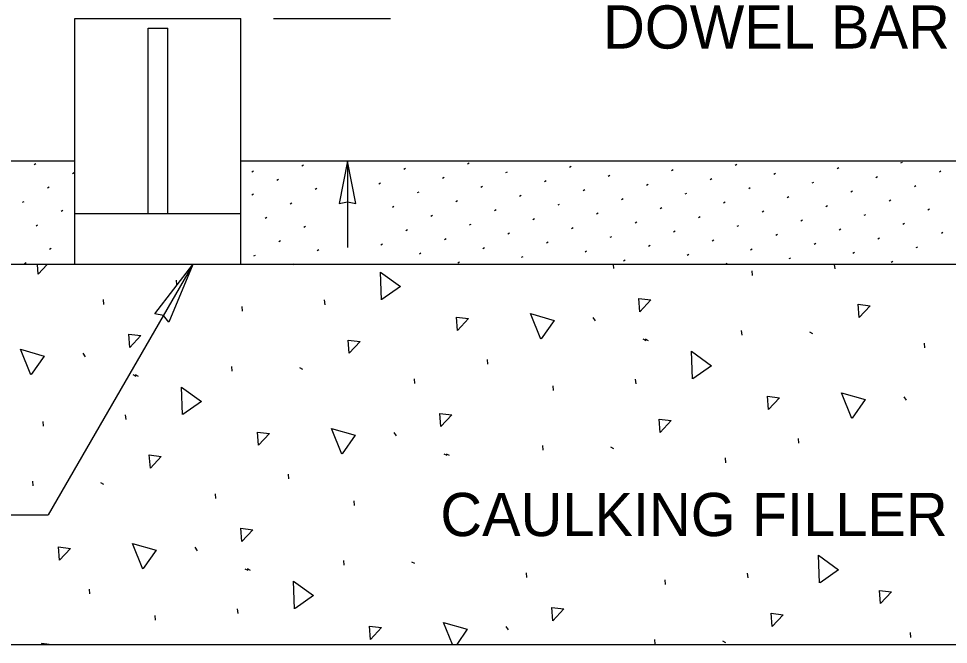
# Model space of a CAD drawing. Extents: x 99862 to 104211, y 98939 to 105076.
# Drawn here: x 100951.2 to 101295.5, y 103804.6 to 104036.3 of the extents above; entities that cross this region are included whole.
import ezdxf

# ---------------------------------------------------------------- set-up
doc = ezdxf.new("R2010")
doc.units = 0
for name, color, linetype in [('Level 1', 7, 'Continuous'), ('Level 15', 7, 'Continuous'), ('Level 2', 7, 'Continuous'), ('Level 20', 7, 'Continuous'), ('Level 3', 7, 'Continuous'), ('Level 4', 7, 'Continuous'), ('Level 6', 7, 'Continuous')]:
    doc.layers.add(name, color=color, linetype=linetype)

msp = doc.modelspace()

# ---------------------------------------------------------------- linework, layer by layer
at = {"layer": 'Level 1'}
msp.add_line((102063.85, 103945.23), (100698.76, 103945.23), dxfattribs=at)
msp.add_line((102063.85, 103945.23), (100698.76, 103945.23), dxfattribs=at)
msp.add_lwpolyline([(100169.63, 103804.62), (100694.77, 103804.62), (102647.84, 103804.62)], dxfattribs=at)
at = {"layer": 'Level 15'}
for p, q in [((101045.5, 104036.29), (101088.91, 104036.29)), ((101072.91, 103983.52), (101072.91, 103951.52)), ((101015.65, 103945.23), (100962.16, 103852.58)), ((100946.16, 103852.58), (100962.16, 103852.58))]:
    msp.add_line(p, q, dxfattribs=at)
for points in [[(101072.91, 103983.52), (101069.82, 103967.79), (101072.91, 103968.52), (101075.99, 103967.79)], [(101015.65, 103945.23), (101006.82, 103923.97), (101004.76, 103926.38), (101001.65, 103926.95)]]:
    msp.add_lwpolyline(points, close=True, dxfattribs=at)
at = {"layer": 'Level 2'}
for p, q in [((100972, 103983.52), (100862.71, 103983.52)), ((101375.26, 103983.52), (101033.5, 103983.52))]:
    msp.add_line(p, q, dxfattribs=at)
at = {"layer": 'Level 3'}
for p, q in [((100956.88, 103982.29), (100957.49, 103982.64)), ((101056.02, 103981.79), (101056.63, 103982.14)), ((101093.83, 103980.53), (101094.43, 103980.88)), ((101117.36, 103982.57), (101117.97, 103982.92)), ((101155.16, 103981.3), (101155.77, 103981.65)), ((101216.5, 103982.07), (101217.11, 103982.42)), ((101254.3, 103980.8), (101254.91, 103981.15)), ((101277.84, 103982.84), (101278.45, 103983.19)), ((100971.15, 103978.98), (100971.75, 103979.33)), ((101037.49, 103979.59), (101038.1, 103979.94)), ((101108.09, 103977.22), (101108.7, 103977.57)), ((101131.63, 103979.26), (101132.23, 103979.61)), ((101169.43, 103977.99), (101170.04, 103978.34)), ((101192.97, 103980.03), (101193.57, 103980.38)), ((101207.23, 103976.72), (101207.84, 103977.07)), ((101230.77, 103978.76), (101231.38, 103979.11)), ((101268.57, 103977.49), (101269.18, 103977.84)), ((101292.11, 103979.53), (101292.71, 103979.88)), ((100961.88, 103973.63), (100962.49, 103973.98)), ((101046.75, 103976.44), (101047.36, 103976.79)), ((101084.56, 103975.17), (101085.16, 103975.52)), ((101122.36, 103973.91), (101122.97, 103974.26)), ((101145.9, 103975.95), (101146.5, 103976.3)), ((101183.7, 103974.68), (101184.31, 103975.03)), ((101221.5, 103973.41), (101222.11, 103973.76)), ((101245.04, 103975.45), (101245.64, 103975.8)), ((101282.84, 103974.18), (101283.45, 103974.53)), ((101037.49, 103971.09), (101038.09, 103971.44)), ((101061.02, 103973.13), (101061.63, 103973.48)), ((101098.83, 103971.86), (101099.43, 103972.21)), ((101136.63, 103970.6), (101137.23, 103970.95)), ((101160.16, 103972.64), (101160.77, 103972.99)), ((101197.97, 103971.37), (101198.57, 103971.72)), ((101235.77, 103970.1), (101236.38, 103970.45)), ((101259.3, 103972.14), (101259.91, 103972.49)), ((100952.61, 103968.28), (100953.22, 103968.63)), ((101051.75, 103967.78), (101052.36, 103968.13)), ((101089.56, 103966.51), (101090.16, 103966.86)), ((101113.09, 103968.56), (101113.7, 103968.91)), ((101150.9, 103967.29), (101151.5, 103967.64)), ((101174.43, 103969.33), (101175.04, 103969.68)), ((101212.23, 103968.06), (101212.84, 103968.41)), ((101250.04, 103966.79), (101250.64, 103967.14)), ((101273.57, 103968.83), (101274.18, 103969.18)), ((100966.88, 103964.97), (100967.49, 103965.32)), ((101103.83, 103963.2), (101104.43, 103963.55)), ((101127.36, 103965.25), (101127.97, 103965.6)), ((101165.16, 103963.98), (101165.77, 103964.33)), ((101188.7, 103966.02), (101189.31, 103966.37)), ((101226.5, 103964.75), (101227.11, 103965.1)), ((101264.3, 103963.48), (101264.91, 103963.83)), ((101287.84, 103965.52), (101288.45, 103965.87)), ((100957.61, 103959.62), (100958.22, 103959.97)), ((101042.49, 103962.43), (101043.09, 103962.78)), ((101118.09, 103959.89), (101118.7, 103960.24)), ((101141.63, 103961.94), (101142.23, 103962.29)), ((101179.43, 103960.67), (101180.04, 103961.02)), ((101202.97, 103962.71), (101203.57, 103963.06)), ((101240.77, 103961.44), (101241.38, 103961.79)), ((101278.57, 103960.17), (101279.18, 103960.52)), ((101056.75, 103959.12), (101057.36, 103959.47)), ((101094.56, 103957.85), (101095.16, 103958.2)), ((101132.36, 103956.59), (101132.97, 103956.94)), ((101155.9, 103958.63), (101156.5, 103958.98)), ((101193.7, 103957.36), (101194.31, 103957.71)), ((101217.23, 103959.4), (101217.84, 103959.75)), ((101231.5, 103956.09), (101232.11, 103956.44)), ((101255.04, 103958.13), (101255.64, 103958.48)), ((101292.84, 103956.86), (101293.45, 103957.21)), ((101047.49, 103953.77), (101048.09, 103954.12)), ((101108.83, 103954.54), (101109.43, 103954.89)), ((101146.63, 103953.28), (101147.23, 103953.63)), ((101170.16, 103955.32), (101170.77, 103955.67)), ((101207.97, 103954.05), (101208.57, 103954.4)), ((101245.77, 103952.78), (101246.38, 103953.13)), ((101269.3, 103954.82), (101269.91, 103955.17)), ((100962.61, 103950.96), (100963.22, 103951.31)), ((101061.75, 103950.46), (101062.36, 103950.81)), ((101085.29, 103952.5), (101085.9, 103952.85)), ((101099.56, 103949.19), (101100.16, 103949.54)), ((101123.09, 103951.23), (101123.7, 103951.58)), ((101160.9, 103949.97), (101161.5, 103950.32)), ((101184.43, 103952.01), (101185.04, 103952.36)), ((101222.23, 103950.74), (101222.84, 103951.09)), ((101260.04, 103949.47), (101260.64, 103949.82)), ((101283.57, 103951.51), (101284.18, 103951.86)), ((101038.22, 103948.42), (101038.83, 103948.77)), ((101113.83, 103945.88), (101114.43, 103946.23)), ((101137.36, 103947.93), (101137.97, 103948.28)), ((101175.16, 103946.66), (101175.77, 103947.01)), ((101198.7, 103948.7), (101199.31, 103949.05)), ((101236.5, 103947.43), (101237.11, 103947.78)), ((101274.3, 103946.16), (101274.91, 103946.51)), ((100953.35, 103945.61), (100953.95, 103945.96)), ((101052.69, 103945.23), (101053.09, 103945.46)), ((101212.97, 103945.39), (101213.57, 103945.74))]:
    msp.add_line(p, q, dxfattribs=at)
at = {"layer": 'Level 4'}
for p, q in [((101171.6, 103943.74), (101171.44, 103945.23)), ((101222.91, 103941.17), (101222.73, 103942.91)), ((101253.49, 103943.62), (101253.32, 103945.23)), ((101009.78, 103937.7), (101009.6, 103939.44)), ((100982.76, 103930.51), (100982.58, 103932.25)), ((101034.08, 103927.94), (101033.89, 103929.68)), ((101064.65, 103930.39), (101064.47, 103932.13)), ((101163.74, 103925.64), (101164.69, 103924.35)), ((101219.08, 103919.04), (101218.9, 103920.78)), ((101243.99, 103920.3), (101245.14, 103919.73)), ((101182.31, 103917.73), (101183.45, 103917.16)), ((101183.12, 103917.73), (101184.27, 103917.16)), ((101286.75, 103914.43), (101286.57, 103916.17)), ((100974.9, 103912.42), (100975.85, 103911.12)), ((101124.94, 103908.39), (101124.75, 103910.13)), ((101030.24, 103905.81), (101030.06, 103907.55)), ((101055.15, 103907.07), (101056.3, 103906.5)), ((100993.47, 103904.5), (100994.62, 103903.93)), ((100994.29, 103904.5), (100995.44, 103903.94)), ((101097.92, 103901.2), (101097.73, 103902.94)), ((101179.81, 103901.08), (101179.63, 103902.82)), ((101149.24, 103898.63), (101149.05, 103900.37)), ((101278.9, 103896.33), (101279.85, 103895.04)), ((100990.98, 103887.86), (100990.79, 103889.6)), ((100960.4, 103885.41), (100960.22, 103887.15)), ((101090.06, 103883.11), (101091.01, 103881.81)), ((101240.1, 103879.08), (101239.91, 103880.82)), ((101145.4, 103876.5), (101145.22, 103878.24)), ((101170.31, 103877.76), (101171.46, 103877.19)), ((101108.63, 103875.19), (101109.78, 103874.62)), ((101109.45, 103875.19), (101110.6, 103874.62)), ((101213.08, 103871.89), (101212.89, 103873.63)), ((101051.26, 103865.86), (101051.08, 103867.6)), ((100956.57, 103863.27), (100956.38, 103865.01)), ((100981.48, 103864.53), (100982.62, 103863.96)), ((101024.24, 103858.66), (101024.06, 103860.4)), ((101075.56, 103856.1), (101075.37, 103857.83)), ((101016.38, 103840.57), (101017.34, 103839.27)), ((101034.95, 103832.65), (101036.1, 103832.08)), ((101035.77, 103832.66), (101036.92, 103832.09)), ((101071.73, 103833.96), (101071.54, 103835.7)), ((101096.63, 103835.22), (101097.78, 103834.65)), ((101139.4, 103829.35), (101139.22, 103831.09)), ((101221.29, 103829.24), (101221.11, 103830.98)), ((101190.72, 103826.78), (101190.53, 103828.52)), ((100977.58, 103823.32), (100977.4, 103825.06)), ((101001.88, 103813.56), (101001.7, 103815.3)), ((101032.46, 103816.01), (101032.27, 103817.75)), ((101131.54, 103811.26), (101132.49, 103809.96)), ((101281.58, 103807.23), (101281.39, 103808.97)), ((101186.88, 103804.65), (101186.7, 103806.39)), ((101211.79, 103805.91), (101212.94, 103805.34))]:
    msp.add_line(p, q, dxfattribs=at)
for points in [[(100958.45, 103941.7), (100958.18, 103945.23)], [(100961.7, 103945.23), (100958.45, 103941.7)], [(101085.55, 103932.21), (101085.18, 103942.45), (101092.58, 103937.09), (101085.71, 103932.3)], [(101181.23, 103927.77), (101180.85, 103932.68), (101185.26, 103932.15), (101181.23, 103927.77)], [(101262.45, 103925.62), (101262.07, 103930.53), (101266.48, 103930), (101262.45, 103925.62)], [(101113.68, 103920.86), (101113.3, 103925.78), (101117.71, 103925.24), (101113.68, 103920.86)], [(101144.57, 103917.61), (101140.71, 103927.1), (101149.51, 103924.59), (101144.68, 103917.74)], [(100992.39, 103914.54), (100992.02, 103919.45), (100996.43, 103918.92), (100992.39, 103914.54)], [(101073.61, 103912.39), (101073.24, 103917.3), (101077.65, 103916.77), (101073.61, 103912.39)], [(100955.73, 103904.38), (100951.88, 103913.87), (100960.67, 103911.37), (100955.85, 103904.51)], [(101200.71, 103902.9), (101200.34, 103913.14), (101207.74, 103907.78), (101200.87, 103902.99)], [(101011.88, 103889.67), (101011.5, 103899.91), (101018.91, 103894.55), (101012.03, 103889.76)], [(101228.84, 103891.55), (101228.46, 103896.47), (101232.87, 103895.93), (101228.84, 103891.55)], [(101259.73, 103888.29), (101255.87, 103897.79), (101264.66, 103895.28), (101259.84, 103888.43)], [(101107.55, 103885.23), (101107.18, 103890.14), (101111.58, 103889.61), (101107.55, 103885.23)], [(101188.77, 103883.08), (101188.4, 103887.99), (101192.8, 103887.46), (101188.77, 103883.08)], [(101070.89, 103875.07), (101067.04, 103884.56), (101075.83, 103882.05), (101071.01, 103875.2)], [(101040, 103878.33), (101039.63, 103883.24), (101044.03, 103882.71), (101040, 103878.33)], [(100999.94, 103869.86), (100999.56, 103874.77), (101003.97, 103874.24), (100999.94, 103869.86)], [(101033.87, 103842.69), (101033.5, 103847.6), (101037.91, 103847.07), (101033.87, 103842.69)], [(100966.32, 103835.79), (100965.95, 103840.7), (100970.36, 103840.17), (100966.32, 103835.79)], [(100997.22, 103832.53), (100993.36, 103842.03), (101002.15, 103839.52), (100997.33, 103832.67)], [(101247.75, 103827.37), (101247.38, 103837.61), (101254.78, 103832.25), (101247.91, 103827.46)], [(101053.36, 103817.82), (101052.98, 103828.06), (101060.39, 103822.7), (101053.51, 103817.91)], [(101270.32, 103819.71), (101269.94, 103824.62), (101274.35, 103824.09), (101270.32, 103819.71)], [(101149.03, 103813.38), (101148.66, 103818.29), (101153.07, 103817.76), (101149.03, 103813.38)], [(101230.25, 103811.23), (101229.88, 103816.15), (101234.29, 103815.61), (101230.25, 103811.23)], [(101111.81, 103804.62), (101108.52, 103812.71), (101117.31, 103810.21), (101113.38, 103804.62)], [(101081.48, 103806.48), (101081.11, 103811.39), (101085.52, 103810.86), (101081.48, 103806.48)], [(100959.86, 103804.62), (100959.82, 103805.07), (100963.51, 103804.62)]]:
    msp.add_lwpolyline(points, dxfattribs=at)
at = {"layer": 'Level 6'}
for p, q in [((100972, 103945.23), (100972, 104036.29)), ((100972, 104036.29), (101033.5, 104036.29)), ((101033.5, 103945.23), (101033.5, 104036.29)), ((100999.08, 104032.75), (101006.42, 104032.75)), ((100999.08, 103964.17), (100999.08, 104032.75)), ((101006.42, 103964.17), (101006.42, 104032.75)), ((100972, 103964.17), (101033.5, 103964.17))]:
    msp.add_line(p, q, dxfattribs=at)

# ---------------------------------------------------------------- texts
at = {"layer": 'Level 20'}
for s, p in [('DOWEL BAR', (101167.59, 104025.19)), ('CAULKING FILLER', (101107.33, 103844.71))]:
    msp.add_text(s, height=16, dxfattribs=at).set_placement(p)

doc.saveas('drawing.dxf')
